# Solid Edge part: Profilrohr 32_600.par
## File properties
Username: ahadarics
Dokumentum tartalom típus: 0
Author: ahadarics
Last saved by: ahadarics
Revision: 93
Sűrűség: 0,000 kg/m^3
Pontosság: 0,990
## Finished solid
Body 1: solid body, 179 faces, 531 edges, 354 vertices.
  Faces by surface: cylinder 109, plane 70
  Edges by curve: line 313, circle 218
Bounding box of the edges (mm): 44.254 x 641.000 x 44.254, from (-22.1268, -608, -22.1268) to (22.1268, 33, 22.1268).
Cylindrical faces by radius (mm): R0.1 x16, R0.2 x30, R0.5 x32, R1 x6, R2.7 x8, R4.5 x4, R4.7 x4, R16 x1, R18 x8
Planar faces by outward normal: +x 4, +y 1, +z 6, -x 6, -y 1, -z 4, oblique 48
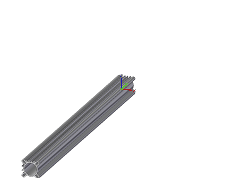
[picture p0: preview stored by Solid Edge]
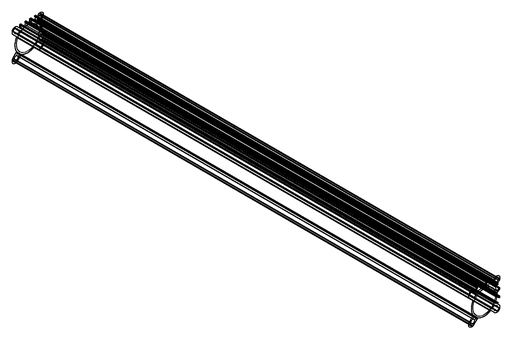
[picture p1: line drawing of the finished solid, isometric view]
